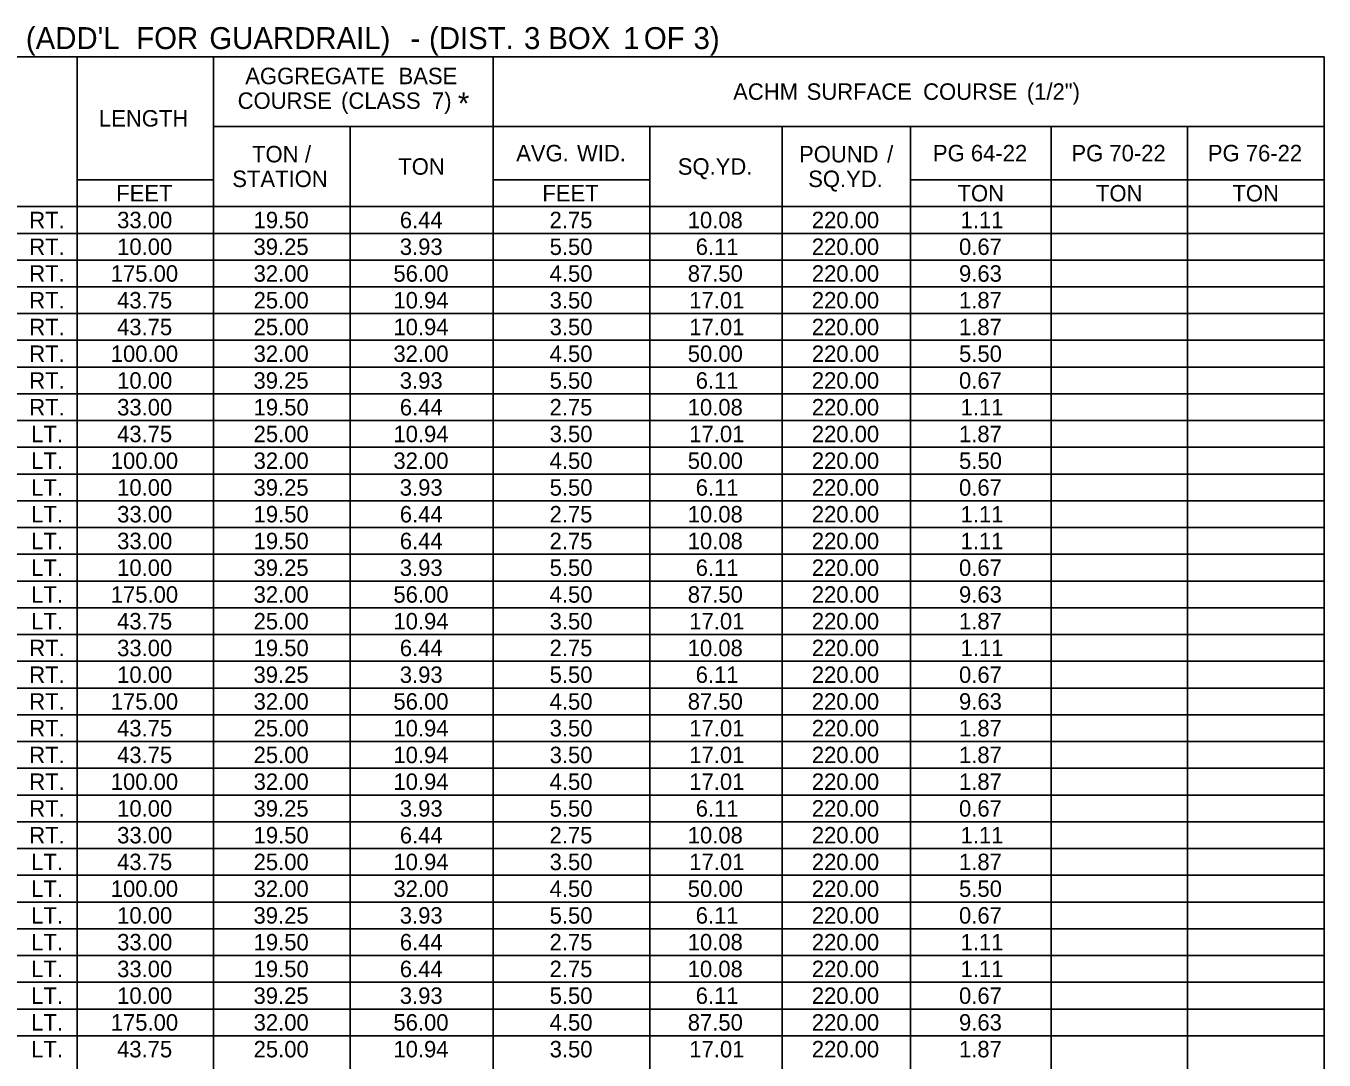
# Model space of a CAD drawing. Extents: x 544478 to 1930787, y -1948294 to 596640.
# Drawn here: x 550607 to 551080, y -1946558.2 to -1946181.2 of the extents above; entities that cross this region are included whole.
import ezdxf

# ---------------------------------------------------------------- set-up
doc = ezdxf.new("R2010")
doc.units = 0
doc.layers.add('Default', color=7, linetype='Continuous')

msp = doc.modelspace()

# ---------------------------------------------------------------- linework, layer by layer
at = {"layer": 'Default'}
for p, q in [((550257.56, -1946192.49), (551079.97, -1946192.49)), ((550625.62, -1946871.09), (550625.62, -1946192.49)), ((550675.35, -1946871.09), (550675.35, -1946192.49)), ((550777.23, -1946880.84), (550777.23, -1946192.49)), ((551079.97, -1946880.84), (551079.97, -1946192.49)), ((550675.35, -1946217.84), (551079.97, -1946217.84)), ((550725.07, -1946880.84), (550725.07, -1946217.84)), ((550834.27, -1946217.84), (550882.53, -1946217.84)), ((550834.27, -1946880.84), (550834.27, -1946217.84)), ((550882.53, -1946880.84), (550882.53, -1946217.84)), ((550929.33, -1946880.84), (550929.33, -1946217.84)), ((550980.52, -1946880.84), (550980.52, -1946217.84)), ((551030.25, -1946880.84), (551030.25, -1946217.84)), ((550625.62, -1946237.34), (550675.35, -1946237.34)), ((550675.35, -1946871.09), (550675.35, -1946237.34)), ((550777.23, -1946237.34), (550834.27, -1946237.34)), ((550777.23, -1946247.09), (550777.23, -1946237.34)), ((550834.27, -1946880.84), (550834.27, -1946237.34)), ((550929.33, -1946237.34), (551079.97, -1946237.34)), ((550257.56, -1946247.09), (551079.97, -1946247.09)), ((550625.62, -1946871.09), (550625.62, -1946247.09)), ((550675.35, -1946247.09), (550834.27, -1946247.09)), ((550725.07, -1946880.84), (550725.07, -1946247.09)), ((550834.27, -1946247.09), (551079.97, -1946247.09)), ((550882.53, -1946880.84), (550882.53, -1946247.09)), ((550503.26, -1946256.84), (551079.97, -1946256.84)), ((550503.26, -1946266.59), (551079.97, -1946266.59)), ((550503.26, -1946276.34), (551079.97, -1946276.34)), ((550503.26, -1946286.09), (551079.97, -1946286.09)), ((550503.26, -1946295.84), (551079.97, -1946295.84)), ((550503.26, -1946305.59), (551079.97, -1946305.59)), ((550503.26, -1946315.34), (551079.97, -1946315.34)), ((550503.26, -1946325.09), (551079.97, -1946325.09)), ((550503.26, -1946334.84), (551079.97, -1946334.84)), ((550503.26, -1946344.59), (551079.97, -1946344.59)), ((550503.26, -1946354.34), (551079.97, -1946354.34)), ((550503.26, -1946364.09), (550777.23, -1946364.09)), ((550725.07, -1946364.09), (550777.23, -1946364.09)), ((550777.23, -1946364.09), (551079.97, -1946364.09)), ((550503.26, -1946373.84), (551079.97, -1946373.84)), ((550503.26, -1946383.59), (550777.23, -1946383.59)), ((550725.07, -1946383.59), (550777.23, -1946383.59)), ((550777.23, -1946383.59), (551079.97, -1946383.59)), ((550503.26, -1946393.34), (550777.23, -1946393.34)), ((550725.07, -1946393.34), (550777.23, -1946393.34)), ((550777.23, -1946393.34), (551079.97, -1946393.34)), ((550257.56, -1946403.09), (551079.97, -1946403.09)), ((550929.33, -1946403.09), (550980.52, -1946403.09)), ((550503.26, -1946412.84), (551079.97, -1946412.84)), ((550503.26, -1946422.59), (551079.97, -1946422.59)), ((550503.26, -1946432.34), (551079.97, -1946432.34)), ((550503.26, -1946442.09), (551079.97, -1946442.09)), ((550503.26, -1946451.84), (551079.97, -1946451.84)), ((550503.26, -1946461.59), (551079.97, -1946461.59)), ((550503.26, -1946471.34), (551079.97, -1946471.34)), ((550503.26, -1946481.09), (551079.97, -1946481.09)), ((550503.26, -1946490.84), (551079.97, -1946490.84)), ((550503.26, -1946500.59), (551079.97, -1946500.59)), ((550503.26, -1946510.34), (551079.97, -1946510.34)), ((550503.26, -1946520.09), (550777.23, -1946520.09)), ((550725.07, -1946520.09), (550777.23, -1946520.09)), ((550777.23, -1946520.09), (551079.97, -1946520.09)), ((550503.26, -1946529.84), (551079.97, -1946529.84)), ((550503.26, -1946539.59), (550777.23, -1946539.59)), ((550725.07, -1946539.59), (550777.23, -1946539.59)), ((550777.23, -1946539.59), (551079.97, -1946539.59)), ((550503.26, -1946549.34), (550777.23, -1946549.34)), ((550725.07, -1946549.34), (550777.23, -1946549.34)), ((550777.23, -1946549.34), (551079.97, -1946549.34))]:
    msp.add_line(p, q, dxfattribs=at)

# ---------------------------------------------------------------- texts
for s, height, p in [(" (ADD'L", 8, (550603.97, -1946189.67)), (' FOR', 8, (550644.17, -1946189.67)), (' GUARDRAIL)', 8, (550670.81, -1946189.67)), (' (DIST.', 8, (550750.87, -1946189.67)), (' 3', 8, (550785.49, -1946189.67)), (' BOX', 8, (550794.32, -1946189.67)), (' 1', 8, (550821.64, -1946189.67)), (' OF', 8, (550829.15, -1946189.67)), (' 3)', 8, (550847.26, -1946189.67)), (' -', 8, (550744.12, -1946189.67)), ('AGGREGATE', 6, (550686.88, -1946202.47)), (' BASE', 6, (550740.5, -1946202.47)), ('ACHM', 6, (550864.67, -1946208.17)), (' SURFACE', 6, (550889.22, -1946208.17)), (' COURSE', 6, (550931.66, -1946208.17)), (' (1/2")', 6, (550969.44, -1946208.17)), ('COURSE', 6, (550684.11, -1946211.47)), (' (CLASS', 6, (550719.57, -1946211.47)), (' 7)', 6, (550752.69, -1946211.47)), ('*', 8, (550764.36, -1946213.47)), ('LENGTH', 6, (550633.57, -1946217.92)), ('TON', 6, (550689.36, -1946230.97)), (' /', 6, (550706.39, -1946230.97)), ('AVG.', 6, (550785.61, -1946230.59)), (' WID.', 6, (550805.53, -1946230.59)), ('POUND', 6, (550888.67, -1946230.97)), (' /', 6, (550918.53, -1946230.97)), ('PG', 6, (550937.46, -1946230.59)), (' 64-22', 6, (550949.06, -1946230.59)), ('PG', 6, (550987.91, -1946230.59)), (' 70-22', 6, (550999.52, -1946230.59)), ('PG', 6, (551037.64, -1946230.59)), (' 76-22', 6, (551049.24, -1946230.59)), ('TON', 6, (550742.64, -1946235.47)), ('SQ.YD.', 6, (550844.48, -1946235.47)), ('STATION', 6, (550682.15, -1946239.97)), ('SQ.YD.', 6, (550892.01, -1946239.97)), ('FEET', 6, (550639.86, -1946245.22)), ('FEET', 6, (550795.13, -1946245.22)), ('TON', 6, (550946.42, -1946245.22)), ('TON', 6, (550996.87, -1946245.22)), ('TON', 6, (551046.6, -1946245.22)), (' RT.', 6, (550605.95, -1946254.97)), ('33.00', 6, (550640.2, -1946254.97)), ('19.50', 6, (550689.93, -1946254.97)), ('6.44', 6, (550743.2, -1946254.97)), ('2.75', 6, (550797.77, -1946254.97)), ('10.08', 6, (550848.1, -1946254.97)), ('220.00', 6, (550893.32, -1946254.97)), ('1.11', 6, (550947.55, -1946254.97)), (' RT.', 6, (550605.95, -1946264.72)), ('10.00', 6, (550640.2, -1946264.72)), ('39.25', 6, (550689.89, -1946264.72)), ('3.93', 6, (550743.19, -1946264.72)), ('5.50', 6, (550797.8, -1946264.72)), ('6.11', 6, (550851.02, -1946264.72)), ('220.00', 6, (550893.32, -1946264.72)), ('0.67', 6, (550946.96, -1946264.72)), (' RT.', 6, (550605.95, -1946274.47)), ('175.00', 6, (550637.87, -1946274.47)), ('32.00', 6, (550689.93, -1946274.47)), ('56.00', 6, (550740.87, -1946274.47)), ('4.50', 6, (550797.8, -1946274.47)), ('87.50', 6, (550848.12, -1946274.47)), ('220.00', 6, (550893.32, -1946274.47)), ('9.63', 6, (550946.96, -1946274.47)), (' RT.', 6, (550605.95, -1946284.22)), ('43.75', 6, (550640.17, -1946284.22)), ('25.00', 6, (550689.93, -1946284.22)), ('10.94', 6, (550740.87, -1946284.22)), ('3.50', 6, (550797.8, -1946284.22)), ('17.01', 6, (550848.69, -1946284.22)), ('220.00', 6, (550893.32, -1946284.22)), ('1.87', 6, (550946.96, -1946284.22)), (' RT.', 6, (550605.95, -1946293.97)), ('43.75', 6, (550640.17, -1946293.97)), ('25.00', 6, (550689.93, -1946293.97)), ('10.94', 6, (550740.87, -1946293.97)), ('3.50', 6, (550797.8, -1946293.97)), ('17.01', 6, (550848.69, -1946293.97)), ('220.00', 6, (550893.32, -1946293.97)), ('1.87', 6, (550946.96, -1946293.97)), (' RT.', 6, (550605.95, -1946303.72)), ('100.00', 6, (550637.87, -1946303.72)), ('32.00', 6, (550689.93, -1946303.72)), ('32.00', 6, (550740.87, -1946303.72)), ('4.50', 6, (550797.8, -1946303.72)), ('50.00', 6, (550848.12, -1946303.72)), ('220.00', 6, (550893.32, -1946303.72)), ('5.50', 6, (550946.98, -1946303.72)), (' RT.', 6, (550605.95, -1946313.47)), ('10.00', 6, (550640.2, -1946313.47)), ('39.25', 6, (550689.89, -1946313.47)), ('3.93', 6, (550743.19, -1946313.47)), ('5.50', 6, (550797.8, -1946313.47)), ('6.11', 6, (550851.02, -1946313.47)), ('220.00', 6, (550893.32, -1946313.47)), ('0.67', 6, (550946.96, -1946313.47)), (' RT.', 6, (550605.95, -1946323.22)), ('33.00', 6, (550640.2, -1946323.22)), ('19.50', 6, (550689.93, -1946323.22)), ('6.44', 6, (550743.2, -1946323.22)), ('2.75', 6, (550797.77, -1946323.22)), ('10.08', 6, (550848.1, -1946323.22)), ('220.00', 6, (550893.32, -1946323.22)), ('1.11', 6, (550947.55, -1946323.22)), (' LT.', 6, (550606.65, -1946332.97)), ('43.75', 6, (550640.17, -1946332.97)), ('25.00', 6, (550689.93, -1946332.97)), ('10.94', 6, (550740.87, -1946332.97)), ('3.50', 6, (550797.8, -1946332.97)), ('17.01', 6, (550848.69, -1946332.97)), ('220.00', 6, (550893.32, -1946332.97)), ('1.87', 6, (550946.96, -1946332.97)), (' LT.', 6, (550606.65, -1946342.72)), ('100.00', 6, (550637.87, -1946342.72)), ('32.00', 6, (550689.93, -1946342.72)), ('32.00', 6, (550740.87, -1946342.72)), ('4.50', 6, (550797.8, -1946342.72)), ('50.00', 6, (550848.12, -1946342.72)), ('220.00', 6, (550893.32, -1946342.72)), ('5.50', 6, (550946.98, -1946342.72)), (' LT.', 6, (550606.65, -1946352.47)), ('10.00', 6, (550640.2, -1946352.47)), ('39.25', 6, (550689.89, -1946352.47)), ('3.93', 6, (550743.19, -1946352.47)), ('5.50', 6, (550797.8, -1946352.47)), ('6.11', 6, (550851.02, -1946352.47)), ('220.00', 6, (550893.32, -1946352.47)), ('0.67', 6, (550946.96, -1946352.47)), (' LT.', 6, (550606.65, -1946362.22)), ('33.00', 6, (550640.2, -1946362.22)), ('19.50', 6, (550689.93, -1946362.22)), ('6.44', 6, (550743.2, -1946362.22)), ('2.75', 6, (550797.77, -1946362.22)), ('10.08', 6, (550848.1, -1946362.22)), ('220.00', 6, (550893.32, -1946362.22)), ('1.11', 6, (550947.55, -1946362.22)), (' LT.', 6, (550606.65, -1946371.97)), ('33.00', 6, (550640.2, -1946371.97)), ('19.50', 6, (550689.93, -1946371.97)), ('6.44', 6, (550743.2, -1946371.97)), ('2.75', 6, (550797.77, -1946371.97)), ('10.08', 6, (550848.1, -1946371.97)), ('220.00', 6, (550893.32, -1946371.97)), ('1.11', 6, (550947.55, -1946371.97)), (' LT.', 6, (550606.65, -1946381.72)), ('10.00', 6, (550640.2, -1946381.72)), ('39.25', 6, (550689.89, -1946381.72)), ('3.93', 6, (550743.19, -1946381.72)), ('5.50', 6, (550797.8, -1946381.72)), ('6.11', 6, (550851.02, -1946381.72)), ('220.00', 6, (550893.32, -1946381.72)), ('0.67', 6, (550946.96, -1946381.72)), (' LT.', 6, (550606.65, -1946391.47)), ('175.00', 6, (550637.87, -1946391.47)), ('32.00', 6, (550689.93, -1946391.47)), ('56.00', 6, (550740.87, -1946391.47)), ('4.50', 6, (550797.8, -1946391.47)), ('87.50', 6, (550848.12, -1946391.47)), ('220.00', 6, (550893.32, -1946391.47)), ('9.63', 6, (550946.96, -1946391.47)), (' LT.', 6, (550606.65, -1946401.22)), ('43.75', 6, (550640.17, -1946401.22)), ('25.00', 6, (550689.93, -1946401.22)), ('10.94', 6, (550740.87, -1946401.22)), ('3.50', 6, (550797.8, -1946401.22)), ('17.01', 6, (550848.69, -1946401.22)), ('220.00', 6, (550893.32, -1946401.22)), ('1.87', 6, (550946.96, -1946401.22)), (' RT.', 6, (550605.95, -1946410.97)), ('33.00', 6, (550640.2, -1946410.97)), ('19.50', 6, (550689.93, -1946410.97)), ('6.44', 6, (550743.2, -1946410.97)), ('2.75', 6, (550797.77, -1946410.97)), ('10.08', 6, (550848.1, -1946410.97)), ('220.00', 6, (550893.32, -1946410.97)), ('1.11', 6, (550947.55, -1946410.97)), (' RT.', 6, (550605.95, -1946420.72)), ('10.00', 6, (550640.2, -1946420.72)), ('39.25', 6, (550689.89, -1946420.72)), ('3.93', 6, (550743.19, -1946420.72)), ('5.50', 6, (550797.8, -1946420.72)), ('6.11', 6, (550851.02, -1946420.72)), ('220.00', 6, (550893.32, -1946420.72)), ('0.67', 6, (550946.96, -1946420.72)), (' RT.', 6, (550605.95, -1946430.47)), ('175.00', 6, (550637.87, -1946430.47)), ('32.00', 6, (550689.93, -1946430.47)), ('56.00', 6, (550740.87, -1946430.47)), ('4.50', 6, (550797.8, -1946430.47)), ('87.50', 6, (550848.12, -1946430.47)), ('220.00', 6, (550893.32, -1946430.47)), ('9.63', 6, (550946.96, -1946430.47)), (' RT.', 6, (550605.95, -1946440.22)), ('43.75', 6, (550640.17, -1946440.22)), ('25.00', 6, (550689.93, -1946440.22)), ('10.94', 6, (550740.87, -1946440.22)), ('3.50', 6, (550797.8, -1946440.22)), ('17.01', 6, (550848.69, -1946440.22)), ('220.00', 6, (550893.32, -1946440.22)), ('1.87', 6, (550946.96, -1946440.22)), (' RT.', 6, (550605.95, -1946449.97)), ('43.75', 6, (550640.17, -1946449.97)), ('25.00', 6, (550689.93, -1946449.97)), ('10.94', 6, (550740.87, -1946449.97)), ('3.50', 6, (550797.8, -1946449.97)), ('17.01', 6, (550848.69, -1946449.97)), ('220.00', 6, (550893.32, -1946449.97)), ('1.87', 6, (550946.96, -1946449.97)), (' RT.', 6, (550605.95, -1946459.72)), ('100.00', 6, (550637.87, -1946459.72)), ('32.00', 6, (550689.93, -1946459.72)), ('10.94', 6, (550740.87, -1946459.72)), ('4.50', 6, (550797.8, -1946459.72)), ('17.01', 6, (550848.69, -1946459.72)), ('220.00', 6, (550893.32, -1946459.72)), ('1.87', 6, (550946.96, -1946459.72)), (' RT.', 6, (550605.95, -1946469.47)), ('10.00', 6, (550640.2, -1946469.47)), ('39.25', 6, (550689.89, -1946469.47)), ('3.93', 6, (550743.19, -1946469.47)), ('5.50', 6, (550797.8, -1946469.47)), ('6.11', 6, (550851.02, -1946469.47)), ('220.00', 6, (550893.32, -1946469.47)), ('0.67', 6, (550946.96, -1946469.47)), (' RT.', 6, (550605.95, -1946479.22)), ('33.00', 6, (550640.2, -1946479.22)), ('19.50', 6, (550689.93, -1946479.22)), ('6.44', 6, (550743.2, -1946479.22)), ('2.75', 6, (550797.77, -1946479.22)), ('10.08', 6, (550848.1, -1946479.22)), ('220.00', 6, (550893.32, -1946479.22)), ('1.11', 6, (550947.55, -1946479.22)), (' LT.', 6, (550606.65, -1946488.97)), ('43.75', 6, (550640.17, -1946488.97)), ('25.00', 6, (550689.93, -1946488.97)), ('10.94', 6, (550740.87, -1946488.97)), ('3.50', 6, (550797.8, -1946488.97)), ('17.01', 6, (550848.69, -1946488.97)), ('220.00', 6, (550893.32, -1946488.97)), ('1.87', 6, (550946.96, -1946488.97)), (' LT.', 6, (550606.65, -1946498.72)), ('100.00', 6, (550637.87, -1946498.72)), ('32.00', 6, (550689.93, -1946498.72)), ('32.00', 6, (550740.87, -1946498.72)), ('4.50', 6, (550797.8, -1946498.72)), ('50.00', 6, (550848.12, -1946498.72)), ('220.00', 6, (550893.32, -1946498.72)), ('5.50', 6, (550946.98, -1946498.72)), (' LT.', 6, (550606.65, -1946508.47)), ('10.00', 6, (550640.2, -1946508.47)), ('39.25', 6, (550689.89, -1946508.47)), ('3.93', 6, (550743.19, -1946508.47)), ('5.50', 6, (550797.8, -1946508.47)), ('6.11', 6, (550851.02, -1946508.47)), ('220.00', 6, (550893.32, -1946508.47)), ('0.67', 6, (550946.96, -1946508.47)), ('33.00', 6, (550640.2, -1946518.22)), ('19.50', 6, (550689.93, -1946518.22)), ('6.44', 6, (550743.2, -1946518.22)), ('2.75', 6, (550797.77, -1946518.22)), ('10.08', 6, (550848.1, -1946518.22)), ('220.00', 6, (550893.32, -1946518.22)), (' LT.', 6, (550606.65, -1946518.22)), ('1.11', 6, (550947.55, -1946518.22)), (' LT.', 6, (550606.65, -1946527.97)), ('33.00', 6, (550640.2, -1946527.97)), ('19.50', 6, (550689.93, -1946527.97)), ('6.44', 6, (550743.2, -1946527.97)), ('2.75', 6, (550797.77, -1946527.97)), ('10.08', 6, (550848.1, -1946527.97)), ('220.00', 6, (550893.32, -1946527.97)), ('1.11', 6, (550947.55, -1946527.97)), (' LT.', 6, (550606.65, -1946537.72)), ('10.00', 6, (550640.2, -1946537.72)), ('39.25', 6, (550689.89, -1946537.72)), ('3.93', 6, (550743.19, -1946537.72)), ('5.50', 6, (550797.8, -1946537.72)), ('6.11', 6, (550851.02, -1946537.72)), ('220.00', 6, (550893.32, -1946537.72)), ('0.67', 6, (550946.96, -1946537.72)), (' LT.', 6, (550606.65, -1946547.47)), ('175.00', 6, (550637.87, -1946547.47)), ('32.00', 6, (550689.93, -1946547.47)), ('56.00', 6, (550740.87, -1946547.47)), ('4.50', 6, (550797.8, -1946547.47)), ('87.50', 6, (550848.12, -1946547.47)), ('220.00', 6, (550893.32, -1946547.47)), ('9.63', 6, (550946.96, -1946547.47)), (' LT.', 6, (550606.65, -1946557.22)), ('43.75', 6, (550640.17, -1946557.22)), ('25.00', 6, (550689.93, -1946557.22)), ('10.94', 6, (550740.87, -1946557.22)), ('3.50', 6, (550797.8, -1946557.22)), ('17.01', 6, (550848.69, -1946557.22)), ('220.00', 6, (550893.32, -1946557.22)), ('1.87', 6, (550946.96, -1946557.22))]:
    msp.add_text(s, height=height, dxfattribs=at).set_placement(p)

doc.saveas('drawing.dxf')
